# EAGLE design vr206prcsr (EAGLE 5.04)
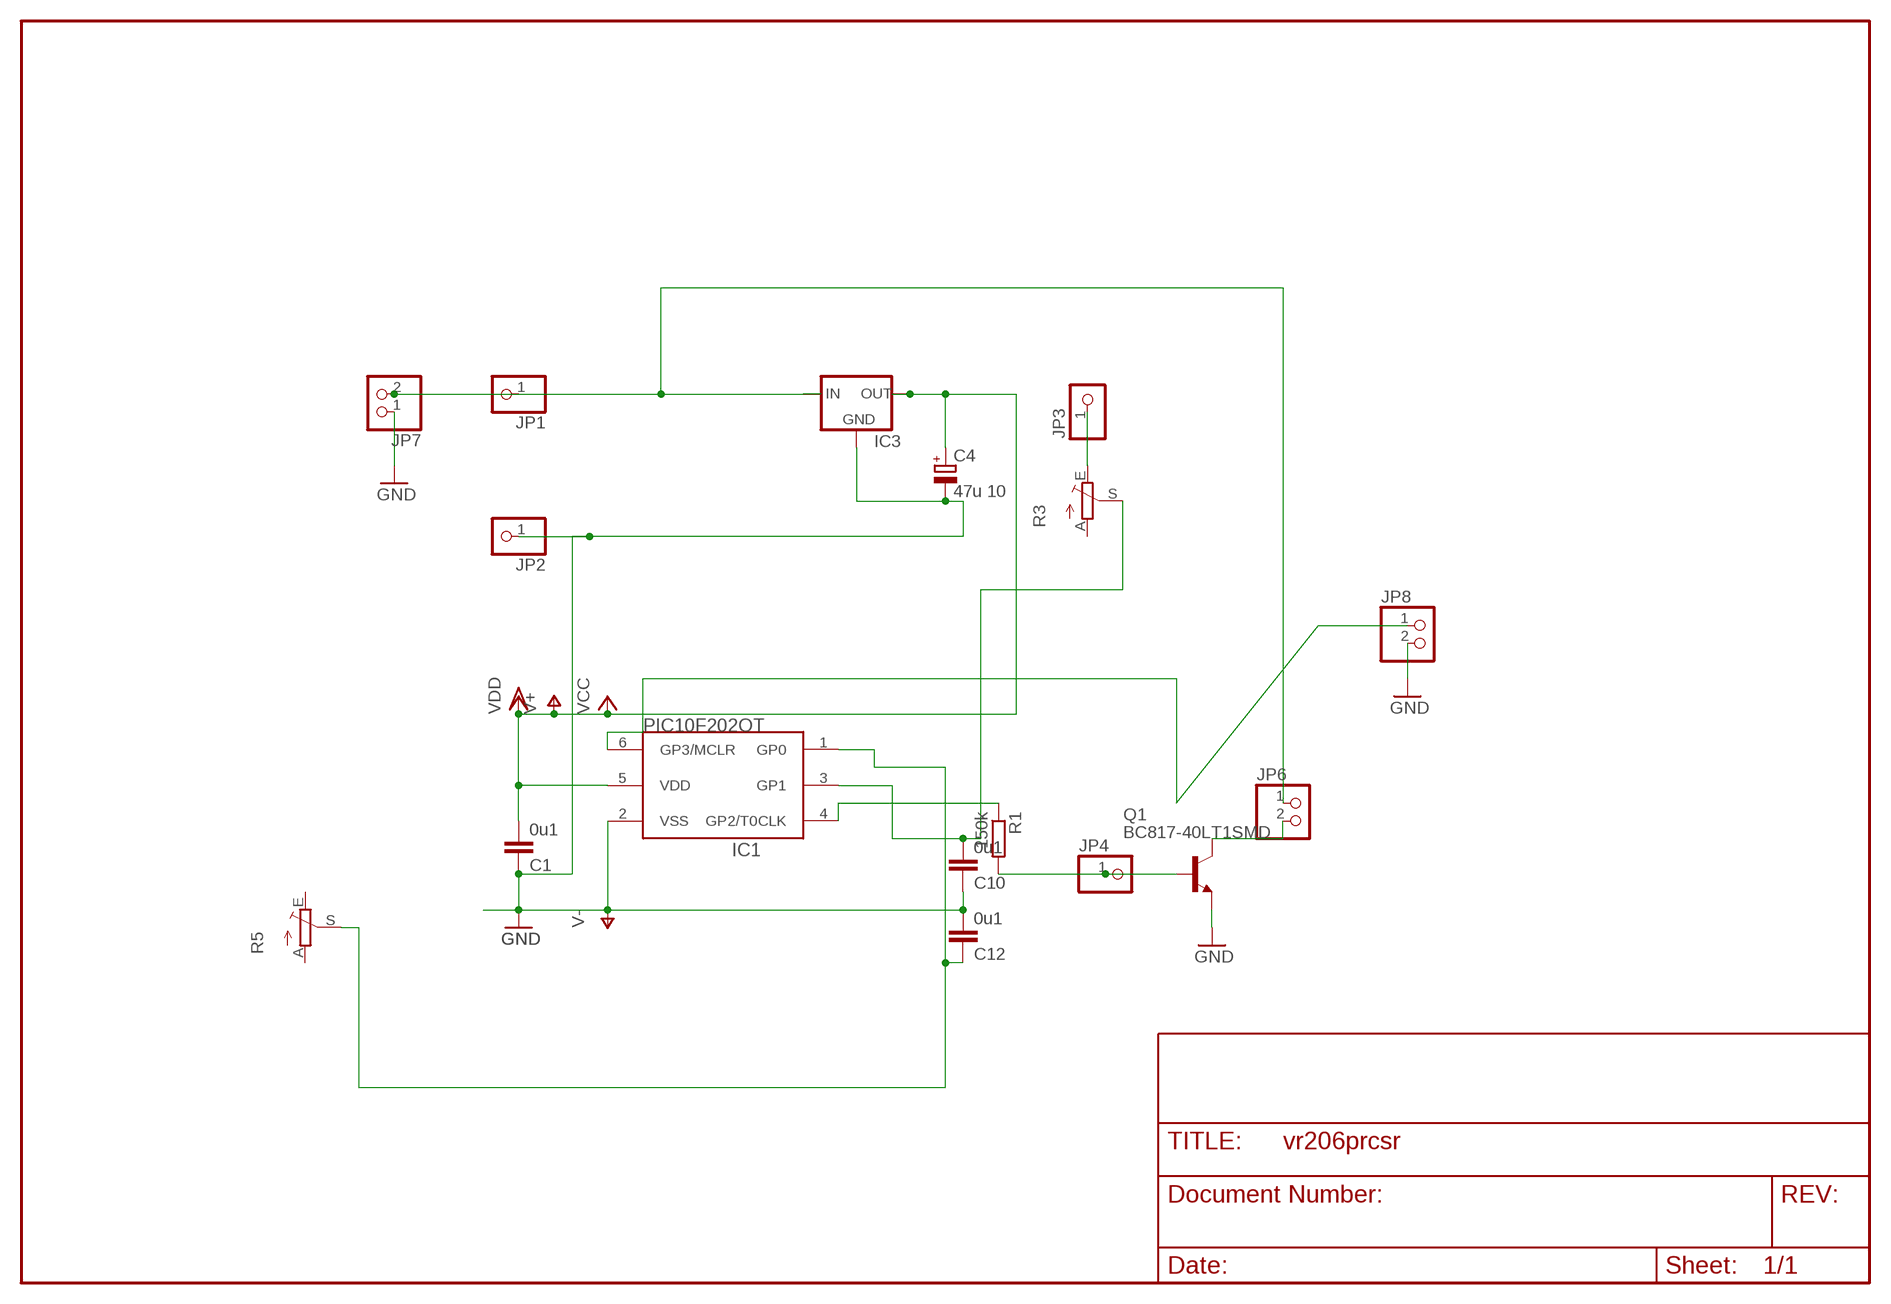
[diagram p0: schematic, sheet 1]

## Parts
C1  0u1  C-EUC1206  [C1206]
C4  47u 10  CPOL-EUE2.5-6  [E2,5-6]
C10  0u1  C-EUC0805  [C0805]
C12  0u1  C-EUC0805  [C0805]
IC1  PIC10F202OT  [SOT23-6]
IC3  78LXX  [78LXX]
JP1  PINHD-1X1  [1X01]
JP2  PINHD-1X1  [1X01]
JP3  PINHD-1X1  [1X01]
JP4  PINHD-1X1  [1X01]
JP6  PINHD-1X2  [1X02]
JP7  PINHD-1X2  [1X02]
JP8  PINHD-1X2  [1X02]
Q1  BC817-40LT1SMD  [SOT23-BEC]
R1  150k  R-EU_R0805  [R0805]
R3  TRIM_EU-CA6V  [CA6V]
R5  TRIM_EU-CA6V  [CA6V]

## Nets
GND: C1.1 C4.- C10.1 C12.2 IC1.2(VSS) IC3.GND JP2.1 JP7.1 JP8.2 Q1.E ; supply symbol labelled V-
N$1: JP3.1 R3.E
N$2: JP4.1 Q1.B R1.2
N$3: IC1.6(GP3/MCLR) JP8.1
N$4: JP6.2 Q1.C
N$5: IC1.4(GP2/T0CLK) R1.1
N$12: C10.2 IC1.3(GP1) R3.S
N$13: C12.1 IC1.1(GP0) R5.S
N$20: IC3.IN JP1.1 JP6.1 JP7.2
V+: C1.2 C4.+ IC1.5(VDD) IC3.OUT ; supply symbol labelled VCC, VDD
Unconnected: R3.A R5.A R5.E

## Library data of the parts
C1 C10 C12 = rcl:C-EU: CAPACITOR, European symbol
C4 = rcl:CPOL-EU: POLARIZED CAPACITOR, European symbol
IC1 = microchip-5:PIC10F20*: uPC nW 0,25/0,5k Program Flash memory
IC3 = v-reg:78LXX: VOLTAGE REGULATOR
JP1-JP4 = pinhead:PINHD-1X1: PIN HEADER
JP6-JP8 = pinhead:PINHD-1X2: PIN HEADER
Q1 = transistor-npn:BC817*: NPN Transistor
R1 = rcl:R-EU_: RESISTOR, European symbol
R3 R5 = pot:TRIM_EU-: POTENTIOMETER

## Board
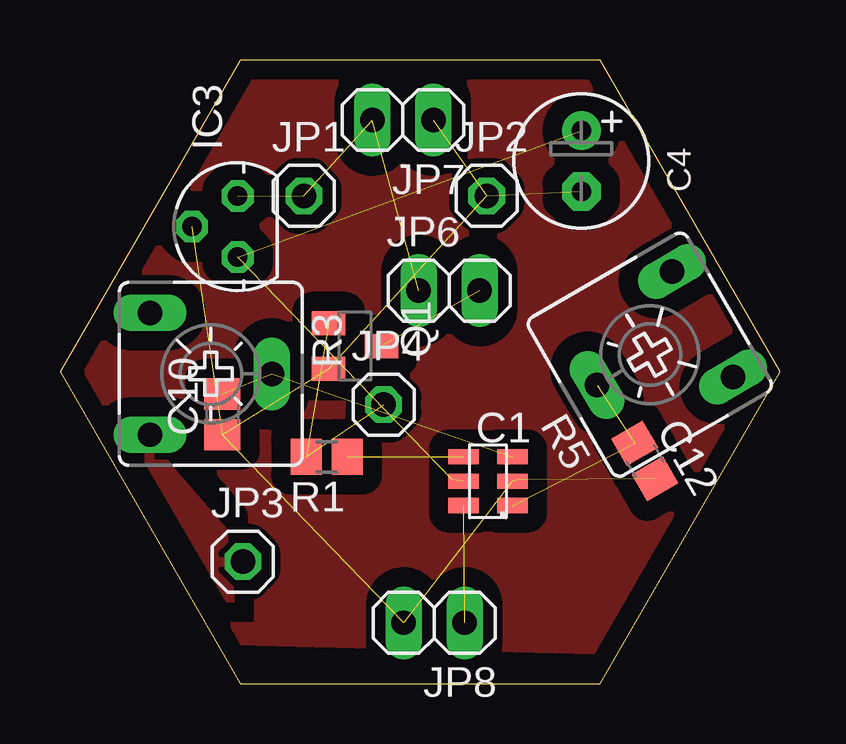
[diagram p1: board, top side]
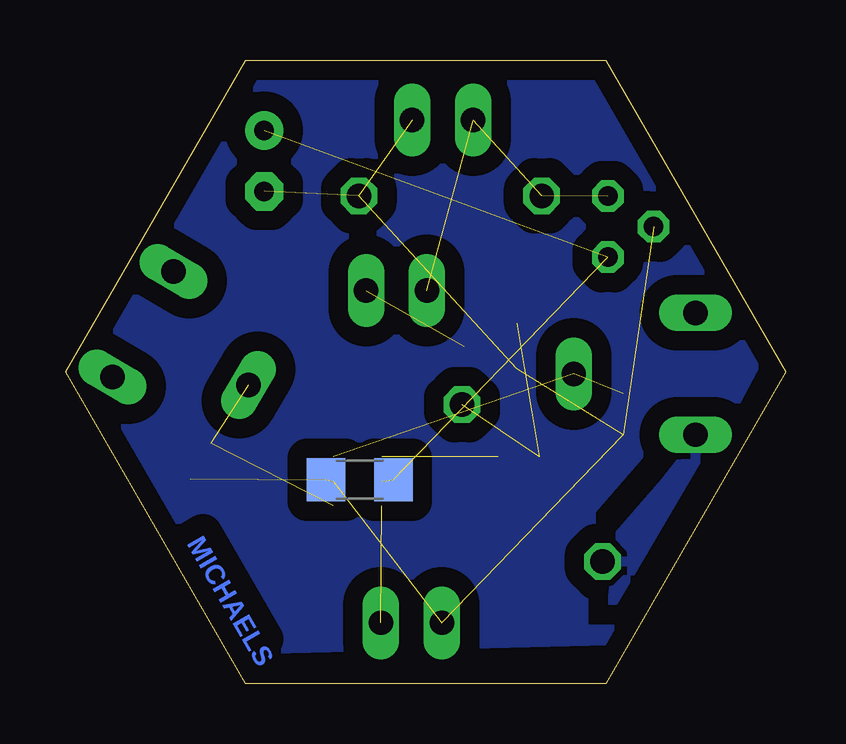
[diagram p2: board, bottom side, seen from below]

Size 30 x 25.98 mm. Coordinates in mm from the lower left corner, seen from the top.
Outline: 7.5,0 22.5,0 30,12.99 22.5,25.98 7.5,25.98 0,12.99 7.5,0
Copper layers (1*16): Top 0.035mm / dielectric 1.5mm / Bottom 0.035mm
Design rules "default *": minimum track width 10mil, minimum drill 24mil, track to track 8mil, track to pad 8mil, pad to pad 8mil, via to via 8mil, smd to smd 8mil, copper to edge 10mil, drill to drill 8mil, minimum pad ring 10mil, minimum via ring 8mil, stop-mask expansion 4mil, vias tented up to drill 0mil, thermal gap 10mil

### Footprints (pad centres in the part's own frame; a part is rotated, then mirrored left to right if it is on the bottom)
C1206 = smd 1.6 x 1.8: 1 -1.4,0; 2 1.4,0
E2,5-6 = drill 0.813 pad 1.6 round: + -1.27,0 | drill 0.813 pad 1.6 octagon: - 1.27,0
C0805 = smd 1.3 x 1.5: 1 -0.85,0; 2 0.85,0
SOT23-6 = smd 0.635 x 1.27: 1 -1.016,-1.016; 2 0,-1.016; 3 1.016,-1.016; 4 1.016,1.016; 5 0,1.016; 6 -1.016,1.016
78LXX = drill 0.813 octagon: GND 0,1.905; IN 1.27,0; OUT -1.27,0
1X01 = drill 1.016 octagon: 1 0,0
1X02 = drill 1.016 long: 1 -1.27,0; 2 1.27,0
SOT23-BEC = smd 1 x 1.4: B -0.95,-1.1; C 0,1.1; E 0.95,-1.1
R0805 = smd 1.3 x 1.5: 1 -0.85,0; 2 0.85,0
CA6V = drill 1.016 long: A -2.54,-2.54; E 2.54,-2.54; S 0,2.54

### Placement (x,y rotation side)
C1  17.74,8.49 0 bottom
C4  21.72,21.77 270 top
C10  6.77,11.21 90 top
C12  24.37,9.27 300 top
IC1  17.83,8.43 90 top
IC3  7.4,19.04 90 top
JP1  10.16,20.32 0 top
JP2  17.78,20.32 0 top
JP3  7.62,5.08 0 top
JP4  13.48,11.62 0 top
JP6  16.21,16.37 0 top
JP7  14.29,23.48 180 top
JP8  15.59,2.53 180 top
Q1  12.29,14.06 270 top
R1  11.11,9.45 180 top
R3  6.29,12.9 270 top
R5  24.58,13.7 120 top

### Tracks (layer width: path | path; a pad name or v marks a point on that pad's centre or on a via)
GND  (9 unrouted)
N$1
  pour Top (isolate 0.61): 2,12.2 7.1,3.5 6.8,6.3 4.9,8.5
  pour Bottom (isolate 0.61): 2.1,12.1 7.2,3.4 6.9,6.2 5,8.4
N$2  (2 unrouted)
N$3  (1 unrouted)
N$4  (1 unrouted)
N$5  (1 unrouted)
N$12  (2 unrouted)
N$13  (2 unrouted)
N$20  (3 unrouted)
V+  (3 unrouted)
V-
  pour Top (isolate 0.813, rank 4): 30.05,13 23.09,1.35 7.34,1.75 0.62,13.77 6.9,25.08 22.48,25.85
  pour Bottom (isolate 0.813, rank 4): 24.25,22.54 29.85,12.7 23.09,1.35 7.34,1.75 0.82,13.97 6.96,25.01 22.34,25.73

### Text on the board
Bottom: MICHAELS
